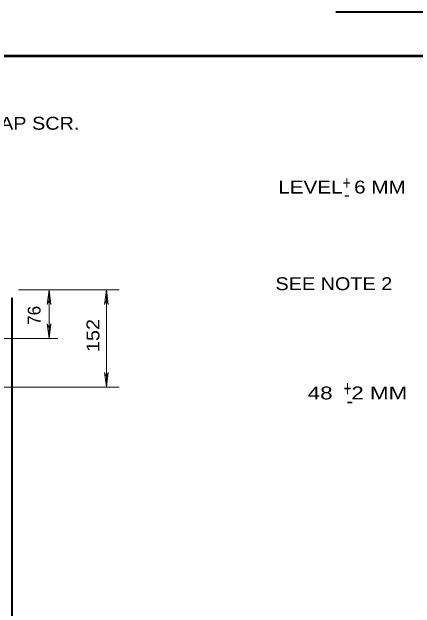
# Model space of a CAD drawing. Extents: x 312583 to 312854, y 144419 to 144597.
# Drawn here: x 312668.62 to 312692.4, y 144453.61 to 144488.78 of the extents above; entities that cross this region are included whole.
import ezdxf
from ezdxf.enums import TextEntityAlignment as Align

# ---------------------------------------------------------------- set-up
doc = ezdxf.new("R2010")
doc.units = 0
doc.header["$LTSCALE"] = 0.3
doc.layers.add('1', color=7, linetype='Continuous', lineweight=13)

msp = doc.modelspace()

# ---------------------------------------------------------------- linework, layer by layer
at = {"layer": '1', "lineweight": 40}
for p, q in [((312687.7256, 144488.7777), (312718.5583, 144488.7777)), ((312668.6224, 144471.9161), (312668.6224, 144429.2664))]:
    msp.add_line(p, q, dxfattribs=at)
at = {"layer": '1', "lineweight": 53}
msp.add_line((312693.5008, 144486.1644), (312666.9226, 144486.1644), dxfattribs=at)
at = {"layer": '1'}
for p, q in [((312669.0057, 144472.3914), (312674.9397, 144472.3914)), ((312670.8074, 144472.3914), (312670.7, 144471.5251)), ((312670.8074, 144469.5164), (312670.8074, 144472.3914)), ((312670.8074, 144472.3914), (312670.9147, 144471.5251)), ((312674.196, 144472.3914), (312674.0887, 144471.5251)), ((312674.196, 144466.6414), (312674.196, 144472.3914)), ((312674.196, 144472.3914), (312674.3034, 144471.5251)), ((312670.7, 144471.5251), (312670.8074, 144471.8011)), ((312670.9147, 144471.5251), (312670.8074, 144471.8011)), ((312674.0887, 144471.5251), (312674.196, 144471.8011)), ((312674.3034, 144471.5251), (312674.196, 144471.8011)), ((312670.7, 144470.3828), (312670.8074, 144470.1068)), ((312670.8074, 144469.5164), (312670.7, 144470.3828)), ((312670.9147, 144470.3828), (312670.8074, 144470.1068)), ((312670.8074, 144469.5164), (312670.9147, 144470.3828)), ((312671.3364, 144469.5164), (312667.388, 144469.5164)), ((312674.0887, 144467.5078), (312674.196, 144467.2318)), ((312674.196, 144466.6414), (312674.0887, 144467.5078)), ((312674.3034, 144467.5078), (312674.196, 144467.2318)), ((312674.196, 144466.6414), (312674.3034, 144467.5078)), ((312667.5337, 144466.6414), (312674.9397, 144466.6414))]:
    msp.add_line(p, q, dxfattribs=at)

# ---------------------------------------------------------------- texts
for s, width, p in [('HEX HEAD CAP SCR.', 1.15, (312660.7794, 144481.8281)), ('LEVEL  6 MM', 1.2, (312684.3265, 144478.0639)), ('SEE NOTE 2', 1.15, (312684.1657, 144472.3633)), ('48   2 MM', 1.3, (312686.0645, 144465.9174))]:
    msp.add_text(s, height=0.76, dxfattribs=dict(at, width=width)).set_placement(p)
for height, width, p in [(0.76, 0.8, (312688.3665, 144478.3175)), (0.92, 0.6, (312688.4117, 144466.109))]:
    msp.add_text('+', height=height, dxfattribs=dict(at, width=width)).set_placement(p, align=Align.CENTER)
for height, p in [(0.76, (312688.3749, 144477.6199)), (0.92, (312688.5498, 144465.3804))]:
    msp.add_text('-', height=height, dxfattribs=at).set_placement(p, align=Align.CENTER)
msp.add_text('76', height=0.76, rotation=90, dxfattribs=at).set_placement((312670.3105, 144470.3093))
at = {"layer": '1', "width": 1.15}
msp.add_text('152 ', height=0.76, rotation=90, dxfattribs=at).set_placement((312673.7791, 144468.7129))

doc.saveas('drawing.dxf')
